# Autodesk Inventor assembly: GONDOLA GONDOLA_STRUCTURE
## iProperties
Shininess: 64.0
Length Units: 11272
Angle Units: 11279
Time Units: 11290
Mass Units: 11286
Length Display Precision: 3
Angle Display Precision: 2
Compacted: True
Part Number: GONDOLA GONDOLA_STRUCTURE
Document SubType Name: Assembly
Created: 2004-08
Designer: John Blackburn
Manufacturer: Standard
Standards Organization: Custom
Density: 0.0
Volumn: 0.0
Area: 0.0
PropertySet Name: Model Information
Control State: 0
Master: False
Checked Out: False
Author: John Blackburn
